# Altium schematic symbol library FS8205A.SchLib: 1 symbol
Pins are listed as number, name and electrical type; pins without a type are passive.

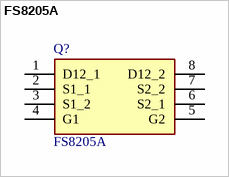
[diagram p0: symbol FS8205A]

## FS8205A
designator Q?
Dual N-Channel Enahncement Mode Power MOSFET; Manufacturer_Name: Fortune Semiconductor Corporation; Geometry.Height: 1.2mm
footprint SOP65P640X120-8N
pins: 1 D12_1, 2 S1_1, 3 S1_2, 4 G1, 5 G2, 6 S2_1, 7 S2_2, 8 D12_2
